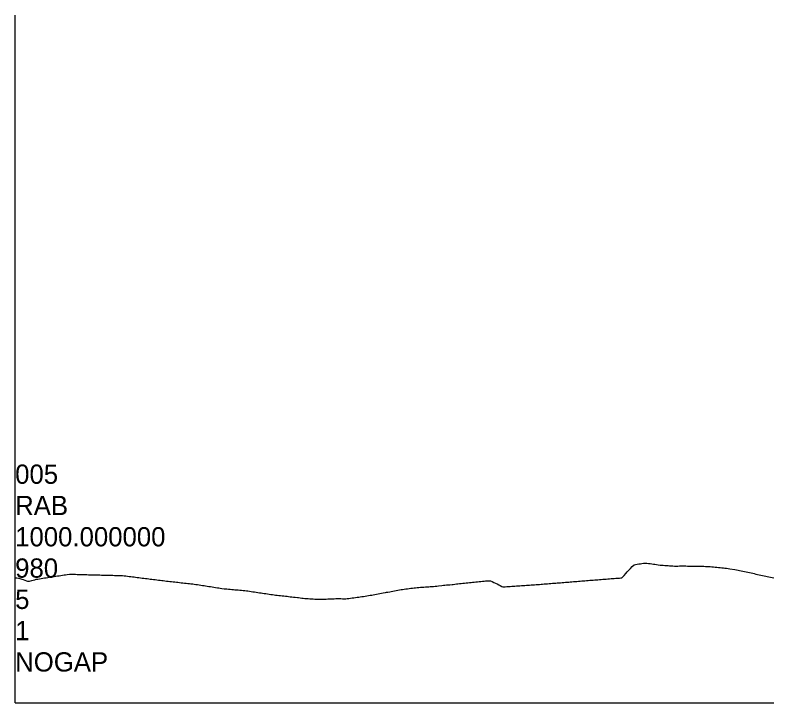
# Model space of a CAD drawing. Extents: x 1615624 to 1632571, y 894455 to 913418.
# Drawn here: x 1632295.4 to 1632571.3, y 901192.7 to 901442.7 of the extents above; entities that cross this region are included whole.
import ezdxf

# ---------------------------------------------------------------- set-up
doc = ezdxf.new("R2010")
doc.units = 0
doc.layers.add('Exist Profile Cell', color=7, linetype='Continuous')
doc.layers.add('Exist Vertical Profile Ground Line', color=7, linetype='Continuous')

msp = doc.modelspace()

# ---------------------------------------------------------------- linework, layer by layer
at = {"layer": 'Exist Profile Cell'}
for q in [(1632295.37, 901442.66), (1632571.26, 901192.66), (1632295.37, 901192.66)]:
    msp.add_line((1632295.37, 901192.66), q, dxfattribs=at)
at = {"layer": 'Exist Vertical Profile Ground Line'}
msp.add_lwpolyline([(1632295.37, 901238.13), (1632295.96, 901238.05), (1632296.56, 901237.96), (1632297.01, 901237.9), (1632297.74, 901237.65), (1632298.33, 901237.44), (1632298.92, 901237.24), (1632299.52, 901237.04), (1632299.88, 901236.92), (1632300.63, 901236.91), (1632301.41, 901237.13), (1632301.88, 901237.26), (1632302.48, 901237.43), (1632303.02, 901237.58), (1632303.66, 901237.68), (1632304.25, 901237.77), (1632304.84, 901237.86), (1632305.44, 901237.95), (1632306.03, 901238.05), (1632306.62, 901238.14), (1632307.21, 901238.23), (1632307.8, 901238.32), (1632308.4, 901238.41), (1632308.99, 901238.5), (1632309.58, 901238.59), (1632310.17, 901238.69), (1632310.76, 901238.78), (1632311.36, 901238.87), (1632311.95, 901238.96), (1632312.54, 901239.05), (1632313.13, 901239.15), (1632313.72, 901239.24), (1632314.32, 901239.33), (1632315.07, 901239.44), (1632315.5, 901239.43), (1632316.09, 901239.41), (1632316.69, 901239.4), (1632317.28, 901239.38), (1632317.87, 901239.36), (1632318.46, 901239.34), (1632319.05, 901239.33), (1632319.65, 901239.31), (1632320.24, 901239.29), (1632320.83, 901239.28), (1632321.42, 901239.26), (1632322.01, 901239.25), (1632322.61, 901239.23), (1632323.2, 901239.21), (1632323.79, 901239.2), (1632324.38, 901239.18), (1632324.97, 901239.17), (1632325.57, 901239.15), (1632326.16, 901239.14), (1632326.75, 901239.12), (1632327.34, 901239.11), (1632327.93, 901239.09), (1632328.53, 901239.08), (1632329.12, 901239.06), (1632329.71, 901239.05), (1632330.3, 901239.04), (1632330.89, 901239.02), (1632331.49, 901239.01), (1632332.08, 901239), (1632332.74, 901238.98), (1632333.26, 901238.96), (1632333.98, 901238.94), (1632334.45, 901238.9), (1632335.04, 901238.86), (1632335.63, 901238.78), (1632336.22, 901238.71), (1632336.81, 901238.63), (1632337.41, 901238.56), (1632338, 901238.48), (1632338.59, 901238.41), (1632339.18, 901238.33), (1632339.77, 901238.26), (1632340.37, 901238.18), (1632340.96, 901238.11), (1632341.55, 901238.03), (1632342.14, 901237.96), (1632342.73, 901237.89), (1632343.33, 901237.81), (1632343.92, 901237.74), (1632344.51, 901237.67), (1632345.1, 901237.59), (1632345.7, 901237.52), (1632346.29, 901237.45), (1632346.88, 901237.38), (1632347.47, 901237.3), (1632348.06, 901237.23), (1632348.66, 901237.16), (1632349.25, 901237.09), (1632349.84, 901237.02), (1632350.43, 901236.95), (1632351.02, 901236.88), (1632351.62, 901236.81), (1632352.21, 901236.74), (1632352.8, 901236.68), (1632353.39, 901236.61), (1632353.98, 901236.54), (1632354.58, 901236.47), (1632355.17, 901236.41), (1632355.76, 901236.34), (1632356.35, 901236.27), (1632356.94, 901236.21), (1632357.54, 901236.15), (1632358.13, 901236.08), (1632358.72, 901236.02), (1632359.31, 901235.96), (1632359.95, 901235.89), (1632360.5, 901235.81), (1632361.09, 901235.72), (1632361.68, 901235.63), (1632362.27, 901235.53), (1632362.86, 901235.44), (1632363.46, 901235.35), (1632364.05, 901235.26), (1632364.64, 901235.17), (1632365.23, 901235.08), (1632365.82, 901234.99), (1632366.42, 901234.9), (1632367.01, 901234.81), (1632367.6, 901234.72), (1632368.19, 901234.62), (1632368.91, 901234.51), (1632369.38, 901234.45), (1632369.97, 901234.36), (1632370.56, 901234.28), (1632371.4, 901234.16), (1632371.75, 901234.12), (1632372.34, 901234.07), (1632372.93, 901234.01), (1632373.52, 901233.95), (1632374.11, 901233.9), (1632374.71, 901233.84), (1632375.3, 901233.79), (1632375.89, 901233.74), (1632376.48, 901233.69), (1632377.07, 901233.63), (1632377.67, 901233.58), (1632378.26, 901233.53), (1632378.85, 901233.48), (1632379.44, 901233.42), (1632380.03, 901233.33), (1632380.63, 901233.24), (1632381.22, 901233.15), (1632381.81, 901233.06), (1632382.4, 901232.97), (1632382.99, 901232.88), (1632383.59, 901232.77), (1632384.18, 901232.68), (1632384.77, 901232.6), (1632385.36, 901232.52), (1632385.95, 901232.44), (1632386.55, 901232.36), (1632387.14, 901232.28), (1632387.74, 901232.21), (1632388.32, 901232.1), (1632388.91, 901232), (1632389.51, 901231.93), (1632390.1, 901231.86), (1632390.69, 901231.79), (1632391.28, 901231.73), (1632391.87, 901231.66), (1632392.47, 901231.59), (1632393.06, 901231.53), (1632393.65, 901231.45), (1632394.24, 901231.38), (1632394.83, 901231.31), (1632395.43, 901231.24), (1632396.02, 901231.17), (1632396.61, 901231.1), (1632397.2, 901231.04), (1632398.03, 901230.95), (1632398.39, 901230.9), (1632398.98, 901230.84), (1632399.57, 901230.77), (1632400.16, 901230.71), (1632400.76, 901230.65), (1632401.51, 901230.57), (1632401.94, 901230.55), (1632402.53, 901230.51), (1632403.12, 901230.48), (1632403.78, 901230.44), (1632404.31, 901230.4), (1632404.9, 901230.36), (1632405.46, 901230.33), (1632406.08, 901230.34), (1632406.68, 901230.35), (1632407.27, 901230.37), (1632407.86, 901230.39), (1632408.45, 901230.4), (1632409.04, 901230.42), (1632409.64, 901230.45), (1632410.23, 901230.47), (1632410.82, 901230.49), (1632411.41, 901230.52), (1632412, 901230.55), (1632412.6, 901230.57), (1632413.19, 901230.6), (1632413.78, 901230.55), (1632414.37, 901230.5), (1632414.93, 901230.45), (1632415.56, 901230.52), (1632416.15, 901230.58), (1632416.74, 901230.65), (1632417.33, 901230.72), (1632417.92, 901230.79), (1632418.52, 901230.87), (1632419.11, 901230.94), (1632419.7, 901231.02), (1632420.29, 901231.11), (1632420.88, 901231.19), (1632421.48, 901231.28), (1632422.07, 901231.37), (1632422.66, 901231.46), (1632423.25, 901231.56), (1632423.84, 901231.65), (1632424.44, 901231.75), (1632425.03, 901231.86), (1632425.62, 901231.96), (1632426.21, 901232.07), (1632426.81, 901232.18), (1632427.4, 901232.29), (1632427.99, 901232.4), (1632428.58, 901232.52), (1632429.17, 901232.63), (1632430.04, 901232.81), (1632430.36, 901232.85), (1632430.95, 901232.91), (1632431.67, 901232.99), (1632432.13, 901233.09), (1632432.73, 901233.21), (1632433.32, 901233.34), (1632433.91, 901233.46), (1632434.5, 901233.59), (1632435.09, 901233.71), (1632435.69, 901233.82), (1632436.28, 901233.92), (1632436.87, 901234.02), (1632437.46, 901234.09), (1632438.05, 901234.16), (1632438.65, 901234.23), (1632439.24, 901234.3), (1632439.83, 901234.36), (1632440.42, 901234.43), (1632441.01, 901234.5), (1632441.61, 901234.56), (1632442.2, 901234.63), (1632442.79, 901234.67), (1632443.38, 901234.71), (1632443.97, 901234.75), (1632444.57, 901234.79), (1632445.16, 901234.83), (1632445.75, 901234.87), (1632446.34, 901234.91), (1632446.93, 901234.94), (1632447.54, 901234.98), (1632448.12, 901235.05), (1632448.71, 901235.13), (1632449.3, 901235.2), (1632450.49, 901235.34), (1632451.08, 901235.39), (1632451.67, 901235.45), (1632452.26, 901235.5), (1632452.85, 901235.56), (1632453.45, 901235.62), (1632454.28, 901235.7), (1632454.63, 901235.74), (1632455.22, 901235.8), (1632455.82, 901235.87), (1632456.41, 901235.93), (1632457, 901236), (1632457.59, 901236.06), (1632458.18, 901236.13), (1632458.78, 901236.19), (1632459.37, 901236.26), (1632460, 901236.33), (1632460.55, 901236.39), (1632461.14, 901236.45), (1632461.74, 901236.51), (1632462.33, 901236.58), (1632462.92, 901236.64), (1632463.51, 901236.71), (1632464.1, 901236.77), (1632464.7, 901236.83), (1632465.29, 901236.9), (1632465.88, 901236.95), (1632466.47, 901236.98), (1632467.06, 901237.01), (1632467.66, 901237.04), (1632468.28, 901237.07), (1632468.84, 901236.77), (1632469.43, 901236.46), (1632470.02, 901236.17), (1632470.62, 901235.88), (1632471.21, 901235.59), (1632471.8, 901235.3), (1632472.39, 901235), (1632472.77, 901234.81), (1632473.58, 901234.87), (1632474.17, 901234.9), (1632474.76, 901234.94), (1632475.35, 901234.98), (1632475.94, 901235.02), (1632476.54, 901235.06), (1632477.13, 901235.1), (1632477.72, 901235.14), (1632478.31, 901235.18), (1632478.9, 901235.23), (1632479.5, 901235.27), (1632480.09, 901235.31), (1632480.68, 901235.35), (1632481.27, 901235.39), (1632481.87, 901235.44), (1632482.46, 901235.48), (1632483.05, 901235.52), (1632483.64, 901235.57), (1632484.23, 901235.61), (1632484.83, 901235.66), (1632485.42, 901235.7), (1632486.01, 901235.74), (1632486.6, 901235.79), (1632487.19, 901235.83), (1632487.79, 901235.88), (1632488.38, 901235.93), (1632488.97, 901235.97), (1632489.56, 901236.02), (1632490.15, 901236.06), (1632490.75, 901236.11), (1632491.34, 901236.16), (1632491.93, 901236.2), (1632492.52, 901236.25), (1632493.11, 901236.3), (1632493.71, 901236.34), (1632494.3, 901236.39), (1632494.89, 901236.44), (1632495.48, 901236.48), (1632496.07, 901236.53), (1632496.67, 901236.58), (1632497.26, 901236.63), (1632497.85, 901236.67), (1632498.44, 901236.72), (1632499.03, 901236.77), (1632499.63, 901236.82), (1632500.22, 901236.86), (1632500.81, 901236.91), (1632501.4, 901236.96), (1632501.99, 901237.01), (1632502.59, 901237.05), (1632503.18, 901237.1), (1632503.77, 901237.15), (1632504.36, 901237.2), (1632504.95, 901237.24), (1632505.55, 901237.29), (1632506.14, 901237.34), (1632506.73, 901237.39), (1632507.32, 901237.43), (1632507.92, 901237.48), (1632508.51, 901237.53), (1632509.1, 901237.57), (1632509.69, 901237.62), (1632510.28, 901237.67), (1632510.88, 901237.71), (1632511.47, 901237.76), (1632512.06, 901237.81), (1632512.65, 901237.85), (1632513.24, 901237.9), (1632513.84, 901237.94), (1632514.43, 901237.99), (1632515.17, 901238.04), (1632515.61, 901238.05), (1632516.02, 901238.05), (1632516.8, 901238.97), (1632517.39, 901239.62), (1632517.98, 901240.27), (1632518.57, 901240.92), (1632519.16, 901241.55), (1632519.76, 901242.18), (1632520.43, 901242.89), (1632520.94, 901242.96), (1632521.53, 901243.05), (1632522.12, 901243.14), (1632522.72, 901243.22), (1632523.31, 901243.3), (1632523.9, 901243.38), (1632524.76, 901243.49), (1632525.08, 901243.45), (1632525.68, 901243.37), (1632526.27, 901243.3), (1632526.86, 901243.22), (1632527.45, 901243.13), (1632528.04, 901243.04), (1632528.64, 901242.95), (1632529.23, 901242.86), (1632529.9, 901242.75), (1632530.41, 901242.72), (1632531, 901242.68), (1632531.6, 901242.64), (1632532.19, 901242.6), (1632532.78, 901242.56), (1632533.37, 901242.51), (1632534.23, 901242.44), (1632534.56, 901242.42), (1632535.15, 901242.39), (1632535.74, 901242.4), (1632536.33, 901242.4), (1632536.93, 901242.41), (1632537.52, 901242.41), (1632538.11, 901242.41), (1632538.7, 901242.41), (1632539.29, 901242.41), (1632539.89, 901242.4), (1632540.48, 901242.4), (1632541.07, 901242.39), (1632541.66, 901242.38), (1632542.25, 901242.37), (1632542.85, 901242.36), (1632543.44, 901242.34), (1632544.03, 901242.33), (1632544.62, 901242.31), (1632545.25, 901242.29), (1632545.81, 901242.29), (1632546.4, 901242.28), (1632546.99, 901242.27), (1632547.58, 901242.25), (1632548.17, 901242.19), (1632548.77, 901242.14), (1632549.36, 901242.08), (1632549.95, 901242.02), (1632550.54, 901241.96), (1632551.13, 901241.9), (1632551.73, 901241.83), (1632552.32, 901241.77), (1632552.91, 901241.7), (1632553.5, 901241.63), (1632554.09, 901241.57), (1632554.69, 901241.49), (1632555.28, 901241.42), (1632557.05, 901241.18), (1632557.65, 901241.06), (1632558.24, 901240.95), (1632558.83, 901240.81), (1632559.42, 901240.68), (1632560.01, 901240.55), (1632560.61, 901240.41), (1632561.2, 901240.28), (1632561.79, 901240.15), (1632562.38, 901240.02), (1632562.98, 901239.88), (1632563.57, 901239.75), (1632564.16, 901239.62), (1632564.75, 901239.49), (1632565.34, 901239.36), (1632565.94, 901239.23), (1632566.53, 901239.1), (1632567.12, 901238.97), (1632567.71, 901238.84), (1632568.3, 901238.71), (1632568.9, 901238.58), (1632569.49, 901238.45), (1632570.08, 901238.33), (1632570.67, 901238.22), (1632571.26, 901238.13)], dxfattribs=at)

# ---------------------------------------------------------------- texts
at = {"layer": 'Exist Profile Cell'}
for s, p in [('005', (1632295.37, 901272.29)), ('RAB', (1632295.37, 901260.91)), ('1000.000000', (1632295.37, 901249.54)), ('980', (1632295.37, 901238.16)), ('5', (1632295.37, 901226.79)), ('1', (1632295.37, 901215.41)), ('NOGAP', (1632295.37, 901204.04))]:
    msp.add_text(s, height=7, dxfattribs=at).set_placement(p)

doc.saveas('drawing.dxf')
